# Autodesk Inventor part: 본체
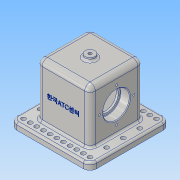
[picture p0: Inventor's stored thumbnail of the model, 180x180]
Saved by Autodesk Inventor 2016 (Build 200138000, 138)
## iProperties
Created: 2018-11
Part Number: 본체
Material: 알루미늄 6061
Document SubType Name: Modeling
Designer: 605-15
Density: 2.7 g/cm^3
Appearance: 알루미늄 - 평지
Mass: 1016.99 g
Surface Area: 777.082 cm^2
Volume: 376.663 cm^3
Author: 605-15
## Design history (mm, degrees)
sketch "스케치1"
  geometry: L1 (-60, 60)-(60, 60); L2 (60, 60)-(60, -60); L3 (60, -60)-(-60, -60); L4 (-60, -60)-(-60, 60); L5 (-60, 60)-(60, -60); L6 (60, 60)-(-60, -60); 1 further point
  constraints: 12 end point, 2 midpoint, 2 parallel, 1 horizontal, 1 perpendicular
  dimensions: "d0" = 120 distance of L2.end L3.end; "d1" = 119.99999 distance of L1.end L2.end
extrude "돌출1" new body sketch "스케치1" distance "d2" = 10; taper "d3" = 0 deg
sketch "스케치2"
  geometry: L1 (40, -40)-(-40, -40); L2 (-40, -40)-(-40, 40); L3 (-40, 40)-(40, 40); L4 (40, 40)-(40, -40); L5 (40, -40)-(-40, 40); L6 (-40, -40)-(40, 40); 1 further point
  constraints: 12 end point, 2 midpoint, 2 parallel, 1 horizontal, 1 perpendicular
  dimensions: "d4" = 80 distance of L1.end L2.end; "d5" = 80 distance of L1.start L1.end
extrude "돌출2" join sketch "스케치2" distance "d6" = 80; taper "d7" = 0 deg
fillet "모깎기1" dims "d8" = 10
fillet "모깎기2" dims "d9" = 3
fillet "모깎기3" dims "d10" = 8
fillet "모깎기4" dims "d11" = 3
sketch "스케치6"
  geometry: L1 (-40, 13)-(-40, 87) reference; L2 (40, 87)-(40, 13) reference; L3 (-40, 48)-(40, 48); L4 (-50, 0)-(50, 0) reference; L5 (-40, 48)-(-40, 68); L6 (-26, 68)-(-26, 64.5); L7 (-40, 68)-(-26, 68); L8 (26, 64.5)-(26, 68); L9 (26, 68)-(40, 68); L10 (-26, 64.5)-(26, 64.5); L11 (40, 68)-(40, 48); 1 further point
  constraints: 16 end point, 4 point on line, 3 perpendicular, 2 horizontal, 1 vertical
  dimensions: "d12" = 48 distance between parallel lines of L4 L3; "d13" = 14 distance of L5.end L6.start; "d16" = 14 distance of L8.end L9.end; "d17" = 20 distance between parallel lines of L3 L7; "d19" = 20 distance between parallel lines of L3 L9; "d20" = 16.5 distance between parallel lines of L3 L10
revolve "회전1" sketch "스케치6" stored, may be unused: angle "d21" = 90 deg
sketch "스케치7"
  geometry: 1 further point
chamfer "모따기1" distance "d22" = 1; stored, may be unused: second distance "d23" = 2, angle "d24" = 45 deg
fillet "모깎기5" dims "d25" = 0.6
sketch "스케치8"
  geometry: L1 (23, 30)-(-23, 30); L2 (-23, 30)-(-23, -30); L3 (-23, -30)-(23, -30); L4 (23, -30)-(23, 30); L5 (23, 30)-(-23, -30); L6 (-23, 30)-(23, -30); 1 further point
  constraints: 12 end point, 2 midpoint, 2 parallel, 1 horizontal, 1 perpendicular
  dimensions: "d26" = 46 distance of L2.end L3.end; "d27" = 60 distance of L1.end L2.end
extrude "돌출3" cut sketch "스케치8" distance "d28" = 80; taper "d29" = 0 deg
fillet "모깎기6" dims "d30" = 3
fillet "모깎기7" dims "d31" = 3
sketch "스케치9"
  geometry: C1 r 7.5 at (0, 0); 1 further point
  constraints: 1 centre point, 1 coincident
  dimensions: "d32" = 15 diameter of C1
extrude "돌출4" join sketch "스케치9" distance "d33" = 5; taper "d34" = 0 deg
fillet "모깎기8" dims "d35" = 3
sketch "스케치11"
  geometry: C1 r 7.5 at (0, 0) reference; 1 further point
  constraints: 1 coincident
hole "구멍1" sketch "스케치11" at (0, 0) diameter "d36" = 4.917; stored, may be unused: countersink angle "d40" = 90 deg, drill point angle "d42" = 118 deg; dims "d37" = 12, "d38" = 4, "d39" = 2, "d41" = 17.1
sketch "스케치13" dims "d43" = 52
  geometry: C1 r 21 at (32, 35) reference; 3 further points
  constraints: 2 vertical alignment, 1 coincident, 2 other
hole "구멍2" sketch "스케치13" at (32, 61) diameter "d44" = 3.242; stored, may be unused: countersink angle "d48" = 90 deg, drill point angle "d50" = 118 deg; dims "d45" = 8, "d46" = 4, "d47" = 2, "d49" = 10
sketch "스케치14"
  geometry: A1 r 7 centre (-50, 50) between (-50, 57) and (-57, 50) reference; 1 further point
hole "구멍3" sketch "스케치14" at (-50, 50) diameter "d54" = 6.6; stored, may be unused: countersink angle "d58" = 90 deg, drill point angle "d60" = 118 deg; dims "d55" = 8, "d56" = 4, "d57" = 2, "d59" = 10
sketch "스케치16"
  geometry: L1 (92, -87)-(82, -87) reference; L2 (82, -87)-(-18, -87) reference; 3 further points
  constraints: 1 midpoint, 1 vertical alignment, 1 other
  dimensions: "d67" = 48 distance from line of L1 point (32, -39)
feature "엠보싱1" sketch "스케치16" dims "d68" = 0.5, "d69" = 0
sketch "스케치18"
  geometry: L1 (37, 32)-(37, -32) reference; L2 (-32, 37)-(32, 37) reference; L3 (-37, -32)-(-37, 32) reference; L4 (32, -37)-(-32, -37) reference; L5 (40, -40)-(-40, -40); L6 (-40, -40)-(-40, 40); L7 (-40, 40)-(40, 40); L8 (40, 40)-(40, -40); L9 (40, -40)-(-40, 40); L10 (-40, -40)-(40, 40); C1 r 10.5 at (0, 0) reference; A1 r 5 centre (32, 32) between (37, 32) and (32, 37) reference; A2 r 5 centre (-32, 32) between (-32, 37) and (-37, 32) reference; A3 r 5 centre (-32, -32) between (-37, -32) and (-32, -37) reference; A4 r 5 centre (32, -32) between (32, -37) and (37, -32) reference
  constraints: 12 end point, 2 midpoint, 2 parallel, 1 horizontal, 1 perpendicular
  dimensions: "d70" = 80 distance of L6.end L7.end; "d71" = 80 distance of L5.end L6.end
extrude "돌출5" join sketch "스케치18" distance "d72" = 5; taper "d73" = 0 deg
fillet "모깎기9" dims "d74" = 8
fillet "모깎기10" dims "d75" = 8
node "솔리드1"
pattern_circular "원형 패턴1" dims angle "d52" = 360 deg
mirror "대칭1"
pattern_linear "직사각형 패턴1" dims "d63" = 10
pattern_linear "직사각형 패턴2" dims "d66" = 25
mirror "대칭2"
mirror "대칭3"
